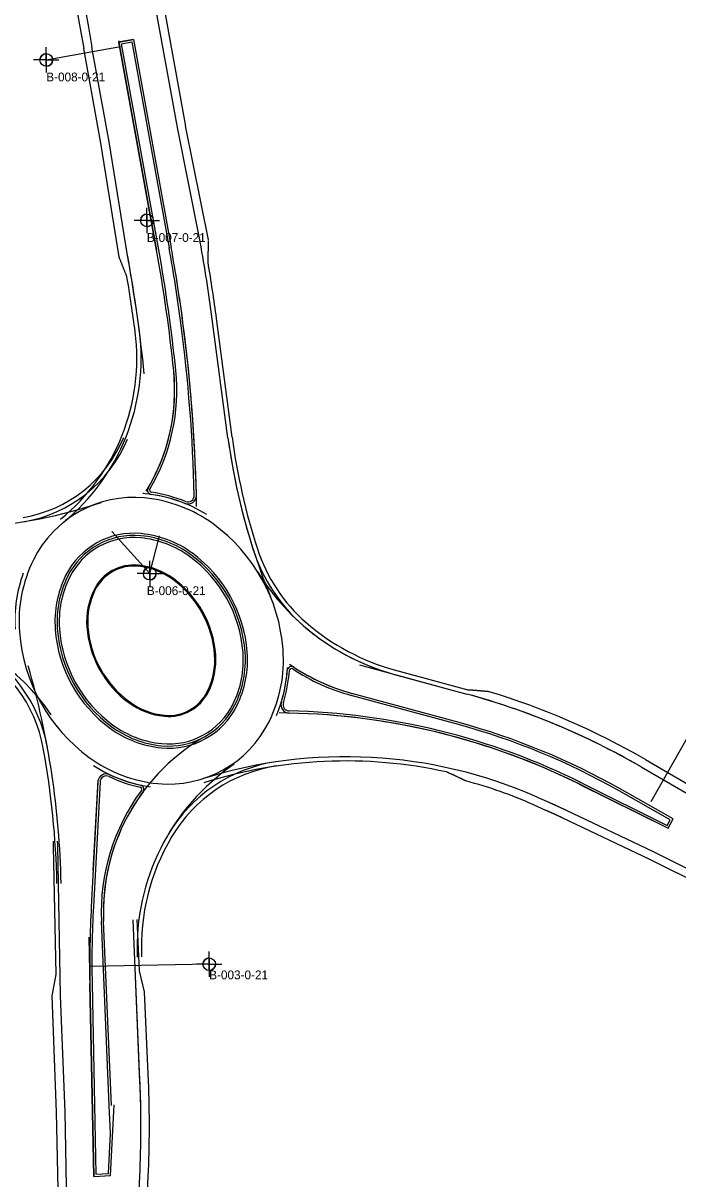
# Model space of a CAD drawing. Extents: x 2047259 to 2048296, y 456488 to 457733.
# Drawn here: x 2047605 to 2047915, y 456763 to 457311 of the extents above; entities that cross this region are included whole.
import ezdxf

# ---------------------------------------------------------------- set-up
doc = ezdxf.new("R2010")
doc.units = 0
for name, color, linetype in [('Default', 7, 'Continuous'), ('DT_X_Break_Line', 7, 'Continuous'), ('DT_X_Contour_Major', 7, 'Continuous'), ('DT_X_Contour_Minor', 7, 'Continuous'), ('DT_X_Contour_Text', 7, 'Continuous'), ('DT_X_Spot_Elev', 7, 'Continuous')]:
    doc.layers.add(name, color=color, linetype=linetype)

msp = doc.modelspace()

# ---------------------------------------------------------------- linework, layer by layer
at = {"layer": 'Default'}
for p, q in [((2047616, 457293.09), (2047651.1, 457299.44)), ((2047663.65, 457217.1), (2047665.94, 457217.51)), ((2047665, 457049.95), (2047647.12, 457069.92)), ((2047665, 457049.95), (2047669.57, 457067.85)), ((2047923.42, 456979.1), (2047902.34, 456941.88)), ((2047693.16, 456865.08), (2047636.81, 456863.99))]:
    msp.add_line(p, q, dxfattribs=at)
at = {"layer": 'DT_X_Break_Line'}
for p, q in [((2047616, 457293.09), (2047616, 457299.09)), ((2047616, 457293.09), (2047610, 457293.09)), ((2047616, 457293.09), (2047613, 457293.09)), ((2047616, 457296.09), (2047616, 457293.09)), ((2047616, 457293.09), (2047616, 457287.09)), ((2047616, 457293.09), (2047622, 457293.09)), ((2047616, 457290.09), (2047616, 457293.09)), ((2047616, 457293.09), (2047619, 457293.09)), ((2047663.65, 457217.1), (2047663.65, 457223.1)), ((2047663.65, 457217.1), (2047657.65, 457217.1)), ((2047663.65, 457217.1), (2047660.65, 457217.1)), ((2047663.65, 457220.1), (2047663.65, 457217.1)), ((2047663.65, 457217.1), (2047663.65, 457211.1)), ((2047663.65, 457217.1), (2047669.65, 457217.1)), ((2047663.65, 457214.1), (2047663.65, 457217.1)), ((2047663.65, 457217.1), (2047666.65, 457217.1)), ((2047665, 457049.95), (2047665, 457055.95)), ((2047665, 457052.95), (2047665, 457049.95)), ((2047665, 457049.95), (2047659, 457049.95)), ((2047665, 457049.95), (2047662, 457049.95)), ((2047665, 457049.95), (2047665, 457043.95)), ((2047665, 457049.95), (2047671, 457049.95)), ((2047665, 457046.95), (2047665, 457049.95)), ((2047665, 457049.95), (2047668, 457049.95)), ((2047693.16, 456865.08), (2047693.16, 456871.08)), ((2047693.16, 456868.08), (2047693.16, 456865.08)), ((2047693.16, 456865.08), (2047687.15, 456865.08)), ((2047693.16, 456865.08), (2047690.16, 456865.08)), ((2047693.16, 456865.08), (2047693.16, 456859.08)), ((2047693.16, 456865.08), (2047699.16, 456865.08)), ((2047693.16, 456862.08), (2047693.16, 456865.08)), ((2047693.16, 456865.08), (2047696.16, 456865.08))]:
    msp.add_line(p, q, dxfattribs=at)
for centre in [(2047616, 457293.09), (2047663.65, 457217.1), (2047665, 457049.95), (2047693.16, 456865.08)]:
    msp.add_circle(centre, 3, dxfattribs=at)
for centre, start, end in [((2047616, 457293.09), 90, 180), ((2047616, 457293.09), 270, 360), ((2047663.65, 457217.1), 90, 180), ((2047663.65, 457217.1), 270, 360), ((2047665, 457049.95), 90, 180), ((2047665, 457049.95), 270, 360), ((2047693.16, 456865.08), 90, 180), ((2047693.16, 456865.08), 270, 360)]:
    msp.add_arc(centre, 3, start, end, dxfattribs=at)
at = {"layer": 'DT_X_Contour_Major'}
for p, q in [((2047678.1, 457261.03), (2047660.18, 457360)), ((2047645.77, 457254.37), (2047637.66, 457299.14)), ((2047688.88, 457207.08), (2047678.1, 457261.03)), ((2047654.5, 457200.56), (2047645.77, 457254.37)), ((2047688.93, 457206.8), (2047688.88, 457207.08)), ((2047688.93, 457206.8), (2047688.88, 457207.08)), ((2047702.06, 457114.21), (2047694.63, 457170.43)), ((2047702.06, 457114.21), (2047694.63, 457170.43)), ((2047764.42, 457006.76), (2047815.15, 456992.93)), ((2047780.92, 457002.26), (2047815.15, 456992.93)), ((2047897.7, 456958.44), (2047973.05, 456914.76)), ((2047848.46, 456944.17), (2047854.07, 456941.7)), ((2047862.22, 456937.97), (2047903.47, 456918.36)), ((2047862.22, 456937.97), (2047903.47, 456918.36)), ((2047622.83, 456850.23), (2047621.45, 456921.04)), ((2047622.83, 456850.23), (2047621.45, 456921.04)), ((2047903.47, 456918.35), (2048068.1, 456836.35)), ((2047660.86, 456798.85), (2047657.12, 456886.11)), ((2047660.4, 456809.46), (2047657.12, 456886.11)), ((2047624.89, 456795.26), (2047622.83, 456850.23)), ((2047630.02, 456531.31), (2047624.89, 456795.26)), ((2047655.6, 456663.75), (2047660.32, 456764.77))]:
    msp.add_line(p, q, dxfattribs=at)
for centre, radius, start, end in [((2049528.91, 457641.59), 1922, 181.11347, 190.26352), ((2046929.29, 457069.25), 772, 7.53092, 10.26352), ((2046929.29, 457069.25), 772, 7.53092, 10.26352), ((2046929.29, 457069.25), 737, 5.86473, 10.22558), ((2046929.29, 457069.25), 737, 7.43955, 10.22558), ((2047560.93, 457151.73), 100, 309.1229, 7.4395), ((2047560.93, 457151.73), 100, 309.1229, 7.4395), ((2047594.5, 457138.58), 65, 279.6381, 337.4418), ((2047999.47, 457153.53), 300, 187.5309, 202.4606), ((2047999.47, 457153.53), 300, 187.5309, 197.9478), ((2047563.52, 457320.97), 250, 260.7593, 288.3105), ((2047563.52, 457320.97), 250, 260.7593, 288.3105), ((2047790.18, 457085.73), 80, 197.9478, 229.0422), ((2047809.84, 457108.39), 110, 211.7205, 254.7532), ((2047531.63, 456923.9), 105, 34.2773, 78.0363), ((2047531.63, 456923.9), 105, 34.2773, 78.0363), ((2047809.84, 457108.39), 110, 229.0422, 254.7532), ((2047547.72, 456954.99), 70, 10.3817, 62.6377), ((2047223.12, 456895.52), 400, 1.1135, 16.069), ((2047223.12, 456895.52), 400, 1.1135, 16.069), ((2047724.16, 456659.11), 346, 60.4781, 74.7532), ((2047724.16, 456659.11), 346, 59.8963, 74.7532), ((2047764.04, 456872.91), 105, 124.1985, 182.4498), ((2047764.04, 456872.91), 105, 124.1985, 182.4498), ((2047735.64, 456889.72), 72, 98.7766, 149.387), ((2047757.79, 456738.25), 225, 66.2355, 107.5448), ((2047757.79, 456738.25), 225, 66.2355, 107.5448), ((2047234.52, 456913.52), 387, 1.1135, 1.4543), ((2047234.52, 456913.52), 387, 1.1135, 1.4543), ((2047160.86, 456788.09), 500, 357.3267, 2.4498)]:
    msp.add_arc(centre, radius, start, end, dxfattribs=at)
for points in [[(2047654.58, 457200.08), (2047654.58, 457200.09), (2047654.58, 457200.11), (2047654.57, 457200.13), (2047654.57, 457200.16), (2047654.57, 457200.18), (2047654.56, 457200.2), (2047654.56, 457200.23), (2047654.55, 457200.25), (2047654.55, 457200.28), (2047654.55, 457200.3), (2047654.54, 457200.32), (2047654.54, 457200.35), (2047654.53, 457200.37), (2047654.53, 457200.4), (2047654.53, 457200.42), (2047654.52, 457200.44), (2047654.52, 457200.47), (2047654.52, 457200.49), (2047654.51, 457200.52), (2047654.51, 457200.54), (2047654.51, 457200.56), (2047654.5, 457200.56)], [(2047854.07, 456941.7), (2047854.2, 456941.64), (2047854.48, 456941.52), (2047854.89, 456941.34), (2047855.3, 456941.16), (2047855.71, 456940.98), (2047856.12, 456940.79), (2047856.53, 456940.61), (2047856.93, 456940.42), (2047857.34, 456940.24), (2047857.75, 456940.05), (2047858.16, 456939.87), (2047858.57, 456939.68), (2047858.97, 456939.49), (2047859.38, 456939.31), (2047859.79, 456939.12), (2047860.2, 456938.93), (2047860.6, 456938.74), (2047861.01, 456938.55), (2047861.41, 456938.36), (2047861.82, 456938.17), (2047862.09, 456938.04), (2047862.22, 456937.97)], [(2047854.07, 456941.7), (2047854.2, 456941.64), (2047854.48, 456941.52), (2047854.89, 456941.34), (2047855.3, 456941.16), (2047855.71, 456940.98), (2047856.12, 456940.79), (2047856.53, 456940.61), (2047856.93, 456940.42), (2047857.34, 456940.24), (2047857.75, 456940.05), (2047858.16, 456939.87), (2047858.57, 456939.68), (2047858.97, 456939.49), (2047859.38, 456939.31), (2047859.79, 456939.12), (2047860.2, 456938.93), (2047860.6, 456938.74), (2047861.01, 456938.55), (2047861.41, 456938.36), (2047861.82, 456938.17), (2047862.09, 456938.04), (2047862.22, 456937.97)]]:
    msp.add_open_spline(points, degree=3, dxfattribs=at)
at = {"layer": 'DT_X_Contour_Minor'}
for p, q in [((2047682.04, 457261.74), (2047664.11, 457360.72)), ((2047641.83, 457253.66), (2047633.73, 457298.43)), ((2047692.81, 457207.87), (2047682.02, 457261.81)), ((2047650.56, 457199.92), (2047641.82, 457253.73)), ((2047899.71, 456961.9), (2047975.06, 456918.22)), ((2047846.85, 456940.51), (2047852.46, 456938.04)), ((2047860.51, 456934.36), (2047901.75, 456914.75)), ((2047901.69, 456914.77), (2048066.32, 456832.77)), ((2047620.9, 456795.11), (2047618.83, 456850.08)), ((2047664.4, 456809.63), (2047662.59, 456851.95)), ((2047626.02, 456531.23), (2047620.89, 456795.18)), ((2047659.59, 456663.57), (2047664.31, 456764.58))]:
    msp.add_line(p, q, dxfattribs=at)
for centre, radius, start, end in [((2049528.91, 457641.59), 1926, 181.11347, 190.26352), ((2047657.47, 457033.03), 36, 84.4396, 153.7154), ((2047656.21, 457020.09), 49, 53.9294, 84.4396), ((2047647.37, 457007.97), 64, 4.2256, 53.9294), ((2047669.12, 457027.27), 49, 153.7154, 184.2256), ((2047684.08, 457028.38), 64, 184.2256, 233.9294), ((2047662.33, 457009.07), 49, 333.7154, 4.2256), ((2047724.16, 456659.11), 350, 59.8963, 73.116), ((2047673.99, 457003.32), 36, 264.4396, 333.7154), ((2047675.25, 457016.25), 49, 233.9294, 264.4396), ((2047757.79, 456738.25), 221, 66.2355, 75.0844), ((2047160.86, 456788.09), 504, 357.3267, 2.4498)]:
    msp.add_arc(centre, radius, start, end, dxfattribs=at)
for points, degree in [([(2047650.63, 457199.45), (2047650.63, 457199.45), (2047650.63, 457199.47), (2047650.62, 457199.49), (2047650.62, 457199.52), (2047650.62, 457199.54), (2047650.61, 457199.57), (2047650.61, 457199.59), (2047650.61, 457199.61), (2047650.6, 457199.64), (2047650.6, 457199.66), (2047650.59, 457199.69), (2047650.59, 457199.71), (2047650.59, 457199.73), (2047650.58, 457199.76), (2047650.58, 457199.78), (2047650.57, 457199.81), (2047650.57, 457199.83), (2047650.57, 457199.85), (2047650.56, 457199.88), (2047650.56, 457199.9), (2047650.56, 457199.92), (2047650.56, 457199.93)], 2), ([(2047852.46, 456938.04), (2047852.53, 456938.01), (2047852.8, 456937.89), (2047853.28, 456937.68), (2047853.67, 456937.51), (2047854.08, 456937.32), (2047854.48, 456937.14), (2047854.88, 456936.96), (2047855.29, 456936.78), (2047855.69, 456936.6), (2047856.09, 456936.41), (2047856.5, 456936.23), (2047856.9, 456936.04), (2047857.3, 456935.86), (2047857.7, 456935.67), (2047858.1, 456935.49), (2047858.51, 456935.3), (2047858.91, 456935.11), (2047859.31, 456934.92), (2047859.69, 456934.75), (2047860.17, 456934.52), (2047860.43, 456934.4), (2047860.51, 456934.36)], 3)]:
    msp.add_open_spline(points, degree=degree, dxfattribs=at)
at = {"layer": 'DT_X_Contour_Text'}
for centre, radius, start, end in [((2047657.47, 457033.03), 53, 84.4396, 153.7154), ((2047656.21, 457020.09), 66, 53.9294, 84.4396), ((2047647.37, 457007.97), 81, 4.2256, 53.9294), ((2047669.12, 457027.27), 66, 153.7154, 184.2256), ((2047684.08, 457028.38), 81, 184.2256, 233.9294), ((2047662.33, 457009.07), 66, 333.7154, 4.2256), ((2047673.99, 457003.32), 53, 264.4396, 333.7154), ((2047675.25, 457016.25), 66, 233.9294, 264.4396)]:
    msp.add_arc(centre, radius, start, end, dxfattribs=at)
at = {"layer": 'DT_X_Spot_Elev'}
for p, q in [((2047657.33, 457302.75), (2047650.14, 457301.44)), ((2047657.33, 457302.75), (2047650.45, 457301.5)), ((2047650.45, 457301.5), (2047657.33, 457302.75)), ((2047650.45, 457301.46), (2047668.27, 457203.06)), ((2047650.45, 457301.46), (2047668.27, 457203.06)), ((2047668.27, 457203.06), (2047650.45, 457301.46)), ((2047651.61, 457300.69), (2047656.53, 457301.58)), ((2047669.25, 457203.24), (2047651.61, 457300.69)), ((2047656.53, 457301.58), (2047674.17, 457204.13)), ((2047657.33, 457302.75), (2047675.16, 457204.3)), ((2047657.33, 457302.75), (2047675.16, 457204.3)), ((2047657.33, 457302.75), (2047675.16, 457204.3)), ((2047692.87, 457207.51), (2047692.87, 457207.54)), ((2047704.04, 457114.47), (2047696.61, 457170.69)), ((2047781.44, 457004.19), (2047815.68, 456994.86)), ((2047811.21, 456978.46), (2047760.47, 456992.29)), ((2047811.47, 456979.42), (2047760.74, 456993.25)), ((2047811.47, 456979.42), (2047760.74, 456993.25)), ((2047811.47, 456979.42), (2047760.74, 456993.25)), ((2047640.48, 456951.38), (2047637.33, 456892.29)), ((2047638.25, 456909.54), (2047640.52, 456952.24)), ((2047641.47, 456951.32), (2047638.33, 456892.23)), ((2047868.39, 456950.35), (2047910.49, 456929.38)), ((2047869.28, 456949.91), (2047910.49, 456929.38)), ((2047869.28, 456949.91), (2047910.49, 456929.38)), ((2047869.72, 456950.81), (2047910.06, 456930.72)), ((2047911.49, 456933.42), (2047887.26, 456947.13)), ((2047912.82, 456933.81), (2047887.76, 456948)), ((2047912.82, 456933.81), (2047887.76, 456948)), ((2047912.82, 456933.81), (2047887.76, 456948)), ((2047910.06, 456930.72), (2047911.49, 456933.42)), ((2047910.49, 456929.38), (2047912.82, 456933.81)), ((2047620.63, 456860.19), (2047619.45, 456921)), ((2047645.87, 456798.21), (2047642.14, 456885.47)), ((2047646.87, 456798.25), (2047643.14, 456885.51)), ((2047646.87, 456798.25), (2047643.14, 456885.51)), ((2047646.87, 456798.25), (2047643.14, 456885.51)), ((2047660.16, 456861.85), (2047659.12, 456886.19)), ((2047638.49, 456764.56), (2047636.29, 456877.88)), ((2047662.59, 456851.95), (2047660.16, 456861.85)), ((2047618.83, 456850.15), (2047620.63, 456860.19)), ((2047638.49, 456764.56), (2047636.72, 456855.98)), ((2047636.72, 456855.98), (2047638.49, 456764.56)), ((2047637.72, 456856), (2047639.47, 456765.62)), ((2047646.43, 456785.08), (2047645.87, 456798.19)), ((2047646.41, 456765.01), (2047648.12, 456798.53)), ((2047645.46, 456765.96), (2047646.43, 456785.08)), ((2047638.49, 456764.56), (2047646.41, 456765.01)), ((2047639.47, 456765.62), (2047645.46, 456765.96))]:
    msp.add_line(p, q, dxfattribs=at)
for centre, radius, start, end in [((2049528.91, 457641.59), 1909, 190.24335, 190.26352), ((2049528.91, 457641.59), 1909, 190.24335, 190.26223), ((2049528.91, 457641.59), 1909, 190.26223, 190.26352), ((2049528.91, 457641.59), 1909, 190.26223, 190.26352), ((2046929.29, 457069.25), 751, 5.86473, 10.26352), ((2046929.29, 457069.25), 751, 5.86473, 10.26352), ((2046929.29, 457069.25), 751, 5.86473, 10.26352), ((2046929.29, 457069.25), 752, 5.86473, 10.26352), ((2046929.29, 457069.25), 757, 7.53944, 10.26352), ((2046929.29, 457069.25), 758, 7.53092, 10.26352), ((2046929.29, 457069.25), 758, 7.53944, 10.26352), ((2046929.29, 457069.25), 758, 7.53944, 10.26352), ((2046929.29, 457069.25), 774, 7.53092, 9.52324), ((2046929.29, 457069.25), 735, 7.43955, 9.48396), ((2046929.29, 457069.25), 757, 1.34055, 7.53944), ((2046929.29, 457069.25), 758, 0.93863, 7.53944), ((2046929.29, 457069.25), 758, 1.34055, 7.53944), ((2046929.29, 457069.25), 758, 1.34055, 7.53944), ((2047560.93, 457151.73), 98, 309.1229, 7.4395), ((2047585.83, 457136.69), 91, 328.3229, 5.8647), ((2047585.83, 457136.69), 91, 329.4485, 5.8647), ((2047585.83, 457136.69), 91, 329.4485, 5.8647), ((2047585.83, 457136.69), 92, 329.4485, 5.8647), ((2047594.5, 457138.58), 63, 279.6381, 337.4418), ((2047999.47, 457153.53), 298, 187.5309, 197.9478), ((2047657.47, 457033.03), 55, 84.4396, 85.5735), ((2047656.21, 457020.09), 68, 58.2681, 84.4396), ((2047665.92, 457089.41), 2, 149.4485, 262.0218), ((2047665.92, 457089.41), 2, 149.4485, 262.0218), ((2047665.92, 457089.41), 1, 149.4485, 262.0218), ((2047656.21, 457020.09), 68, 68.0832, 82.0218), ((2047656.21, 457020.09), 68, 68.0832, 82.0218), ((2047656.21, 457020.09), 69, 68.0832, 82.0218), ((2047683.08, 457086.89), 4, 248.0832, 1.3405), ((2047683.08, 457086.89), 4, 248.0832, 1.3405), ((2047683.08, 457086.89), 3, 248.0832, 1.3405), ((2047657.47, 457033.03), 35, 84.4396, 153.7154), ((2047657.47, 457033.03), 34, 84.4396, 153.7154), ((2047656.21, 457020.09), 47, 53.9294, 84.4396), ((2047656.21, 457020.09), 48, 53.9294, 84.4396), ((2047647.37, 457007.97), 62, 4.2256, 53.9294), ((2047647.37, 457007.97), 63, 4.2256, 53.9294), ((2047790.18, 457085.73), 78, 197.9478, 229.0422), ((2047657.47, 457033.03), 21, 84.4396, 153.7154), ((2047657.47, 457033.03), 20.5, 84.4396, 153.7154), ((2047656.21, 457020.09), 33.5, 53.9294, 84.4396), ((2047656.21, 457020.09), 34, 53.9294, 84.4396), ((2047669.12, 457027.27), 68, 160.2692, 183.0742), ((2047669.12, 457027.27), 48, 153.7154, 184.2256), ((2047669.12, 457027.27), 47, 153.7154, 184.2256), ((2047647.37, 457007.97), 48.5, 4.2256, 53.9294), ((2047647.37, 457007.97), 49, 4.2256, 53.9294), ((2047669.12, 457027.27), 34, 153.7154, 184.2256), ((2047669.12, 457027.27), 33.5, 153.7154, 184.2256), ((2047809.84, 457108.39), 108, 229.0422, 254.7532), ((2047684.08, 457028.38), 63, 184.2256, 233.9294), ((2047684.08, 457028.38), 62, 184.2256, 233.9294), ((2047684.08, 457028.38), 49, 184.2256, 233.9294), ((2047684.08, 457028.38), 48.5, 184.2256, 233.9294), ((2047547.72, 456954.99), 68, 10.3817, 62.6377), ((2047662.33, 457009.07), 33.5, 333.7154, 4.2256), ((2047662.33, 457009.07), 34, 333.7154, 4.2256), ((2047662.33, 457009.07), 47, 333.7154, 4.2256), ((2047662.33, 457009.07), 48, 333.7154, 4.2256), ((2047662.33, 457009.07), 68, 337.2984, 357.0436), ((2047662.33, 457009.07), 68, 342.9242, 355.8302), ((2047662.33, 457009.07), 68, 342.9242, 355.8302), ((2047662.33, 457009.07), 69, 342.9242, 355.8302), ((2047732.15, 457003.98), 2, 56.6805, 175.8302), ((2047732.15, 457003.98), 2, 56.6805, 175.8302), ((2047732.15, 457003.98), 1, 56.6805, 175.8302), ((2047785.98, 457085.87), 96, 235.1779, 254.7532), ((2047785.98, 457085.87), 97, 236.6805, 254.7532), ((2047785.98, 457085.87), 96, 236.6805, 254.7532), ((2047785.98, 457085.87), 96, 236.6805, 254.7532), ((2047673.99, 457003.32), 21, 264.4396, 333.7154), ((2047673.99, 457003.32), 20.5, 264.4396, 333.7154), ((2047675.25, 457016.25), 34, 233.9294, 264.4396), ((2047675.25, 457016.25), 33.5, 233.9294, 264.4396), ((2047673.99, 457003.32), 35, 264.4396, 333.7154), ((2047673.99, 457003.32), 34, 264.4396, 333.7154), ((2047731.16, 456987.93), 4, 162.9242, 268.8187), ((2047731.16, 456987.93), 4, 162.9242, 268.8187), ((2047731.16, 456987.93), 3, 162.9242, 268.8187), ((2047724.38, 456659), 325, 63.5225, 89.6669), ((2047724.38, 456659), 325, 63.5225, 88.8187), ((2047724.38, 456659), 325, 63.5225, 88.8187), ((2047724.38, 456659), 326, 63.5225, 88.8187), ((2047675.25, 457016.25), 48, 233.9294, 264.4396), ((2047675.25, 457016.25), 47, 233.9294, 264.4396), ((2047724.16, 456659.11), 331, 60.4781, 74.7532), ((2047724.16, 456659.11), 332, 60.4781, 74.7532), ((2047724.16, 456659.11), 332, 60.4781, 74.7532), ((2047724.16, 456659.11), 332, 60.4781, 74.7532), ((2047739.05, 456889.61), 96, 121.3913, 182.4498), ((2047223.12, 456895.52), 398, 1.1135, 10.3817), ((2047757.79, 456738.25), 223, 77.6308, 107.5448), ((2047675.25, 457016.25), 68, 237.1764, 261.6153), ((2047644.47, 456951.16), 4, 64.6916, 176.9515), ((2047644.47, 456951.16), 4, 64.6916, 176.9515), ((2047644.47, 456951.16), 3, 64.6916, 176.9515), ((2047675.25, 457016.25), 69, 244.6916, 257.6282), ((2047675.25, 457016.25), 68, 244.6916, 257.6282), ((2047675.25, 457016.25), 68, 244.6916, 257.6282), ((2047735.64, 456889.72), 70, 98.7766, 149.387), ((2047660.25, 456947.88), 1, 323.5182, 77.6282), ((2047660.25, 456947.88), 2, 323.5182, 77.6282), ((2047660.25, 456947.88), 2, 323.5182, 77.6282), ((2047723.49, 456659.44), 325, 63.5225, 63.5314), ((2047739.05, 456889.61), 97, 143.5182, 182.4498), ((2047739.05, 456889.61), 96, 143.5182, 182.4498), ((2047739.05, 456889.61), 96, 143.5182, 182.4498), ((2047234.52, 456913.52), 385, 1.1135, 1.4543), ((2047764.04, 456872.91), 103, 149.387, 182.4498), ((2048136.62, 456865.7), 500, 176.9515, 181.1135), ((2048136.62, 456865.7), 500, 176.9515, 181.1135), ((2048136.62, 456865.7), 499, 176.9515, 181.1135), ((2047148.33, 456776.92), 498, 2.4471, 2.4498), ((2047148.33, 456776.92), 499, 2.4471, 2.4498), ((2047148.33, 456776.92), 499, 2.4471, 2.4498), ((2047148.33, 456776.92), 499, 2.4471, 2.4498)]:
    msp.add_arc(centre, radius, start, end, dxfattribs=at)
for points in [[(2047692.62, 457197.3), (2047692.63, 457197.47), (2047692.64, 457197.81), (2047692.65, 457198.32), (2047692.67, 457198.83), (2047692.68, 457199.34), (2047692.7, 457199.85), (2047692.71, 457200.36), (2047692.72, 457200.87), (2047692.74, 457201.38), (2047692.75, 457201.89), (2047692.76, 457202.4), (2047692.77, 457202.91), (2047692.78, 457203.43), (2047692.8, 457203.94), (2047692.81, 457204.45), (2047692.82, 457204.96), (2047692.83, 457205.47), (2047692.84, 457205.98), (2047692.85, 457206.49), (2047692.86, 457207), (2047692.86, 457207.34), (2047692.87, 457207.51)], [(2047654.24, 457190.35), (2047654.18, 457190.51), (2047654.06, 457190.81), (2047653.89, 457191.26), (2047653.71, 457191.71), (2047653.53, 457192.16), (2047653.35, 457192.62), (2047653.17, 457193.07), (2047653, 457193.52), (2047652.82, 457193.97), (2047652.64, 457194.42), (2047652.46, 457194.87), (2047652.28, 457195.32), (2047652.1, 457195.77), (2047651.92, 457196.22), (2047651.74, 457196.68), (2047651.55, 457197.13), (2047651.37, 457197.58), (2047651.19, 457198.02), (2047651.01, 457198.47), (2047650.83, 457198.92), (2047650.71, 457199.22), (2047650.65, 457199.37)], [(2047825.81, 456994.02), (2047825.64, 456994.04), (2047825.31, 456994.07), (2047824.8, 456994.12), (2047824.29, 456994.17), (2047823.78, 456994.21), (2047823.28, 456994.26), (2047822.77, 456994.31), (2047822.26, 456994.35), (2047821.76, 456994.39), (2047821.25, 456994.44), (2047820.74, 456994.48), (2047820.23, 456994.52), (2047819.73, 456994.56), (2047819.22, 456994.6), (2047818.72, 456994.64), (2047818.21, 456994.68), (2047817.7, 456994.72), (2047817.2, 456994.75), (2047816.69, 456994.79), (2047816.18, 456994.83), (2047815.85, 456994.85), (2047815.68, 456994.86)], [(2047814.68, 456951.8), (2047814.53, 456951.88), (2047814.23, 456952.02), (2047813.78, 456952.25), (2047813.33, 456952.47), (2047812.88, 456952.69), (2047812.43, 456952.9), (2047811.97, 456953.12), (2047811.52, 456953.34), (2047811.06, 456953.56), (2047810.61, 456953.77), (2047810.15, 456953.98), (2047809.7, 456954.2), (2047809.24, 456954.41), (2047808.78, 456954.62), (2047808.33, 456954.83), (2047807.87, 456955.04), (2047807.41, 456955.25), (2047806.95, 456955.46), (2047806.49, 456955.66), (2047806.02, 456955.87), (2047805.72, 456956), (2047805.56, 456956.07)]]:
    msp.add_open_spline(points, degree=3, dxfattribs=at)

# ---------------------------------------------------------------- texts
at = {"layer": 'Default'}
for s, p in [('B-008-0-21', (2047616, 457282.92)), ('B-007-0-21', (2047663.65, 457206.93)), ('B-006-0-21', (2047663.64, 457039.78)), ('B-003-0-21', (2047693.16, 456857.92))]:
    msp.add_text(s, height=4.167, dxfattribs=at).set_placement(p)

doc.saveas('drawing.dxf')
